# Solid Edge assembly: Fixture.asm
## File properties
Author: Sarvanan
Template: sync ansi assembly.asm
Last saved by: CADCIM
Revision: 7
Application: Solid Edge
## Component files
end plate.par
disk.par
support pin.par
spacer.par
center pin.par
bolt.par
nut.par
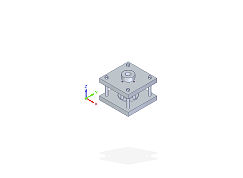
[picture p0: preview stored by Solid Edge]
